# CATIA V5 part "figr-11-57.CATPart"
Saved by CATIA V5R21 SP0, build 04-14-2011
Part number: Part1
Bounding box of the stored display mesh (mm): x -55 to 55, y -105 to 155, z -20 to 14.953
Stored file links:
  D:\CATIA V5R21 E-RESOURCES\CATIA-V5R21\catia-v5r21-prt\c11-catia-v5r21-prt\c11-catia-v5r21-figr-11-57.CATPart
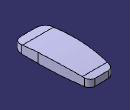
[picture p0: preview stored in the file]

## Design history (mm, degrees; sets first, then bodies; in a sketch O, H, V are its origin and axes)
Set1
  Extrude1: Element1 Sketch2, Lim1 50, Lim2 50, Direction yz-plane
  Sketch1 on xy-plane, origin (0, 0, 0), H (1, 0, 0), V (0, 1, 0)
    arc A1 centre (25, -75) radius 25 from (25, -100) to (50, -75) ccw
    line L1 (50, -75) -> (50, -15)
    point P4 (50, -15)
    arc A2 centre (-950, -15) radius 1000 from (50, -15) to (38.3367, 137.2843) ccw
    line L2 (23.5117, 150) -> (-23.5117, 150)
    line L3 (25, -100) -> (-25, -100)
    arc A3 centre (-25, -75) radius 25 from (-25, -100) to (-50, -75) cw
    line L4 (-50, -75) -> (-50, -15)
    point P9 (-50, -15)
    arc A4 centre (950, -15) radius 1000 from (-50, -15) to (-38.3367, 137.2843) cw
    reference projected line E1 (-50, -100) -> (50, -100) from edge of Extrude1
    axis line L5 (0, 170.4214) -> (0, -120.6595)
    point P11 (0, 170.4214)
    reference projected line E2 (50, -70) -> (50, 129.9971) from edge of Extrude1
    reference projected line E3 (-50, 129.9971) -> (-50, -70) from edge of Extrude1
    reference projected line E4 (-50, -100) -> (50, -100) from edge of Extrude1
    reference projected line E5 (50, 150) -> (-50, 150) from edge of Extrude1
    arc A5 centre (-23.5117, 135) radius 15 from (-38.3367, 137.2843) to (-23.5117, 150) cw
    arc A6 centre (23.5117, 135) radius 15 from (38.3367, 137.2843) to (23.5117, 150) ccw
    distance E4 P4 = 85
    radius A2 = 1000
    radius A5 = 15
    radius A6 = 15
    radius A1 = 25
    radius A3 = 25
    radius A4 = 1000
    tangency: L1 A1, A2 L1, L3 A1, A3 L3, A4 L4, L5 A3, A5 L2, A5 A4, A6 A2, A6 L2, A3 L4
    horizontal: L2 H
    coincidence: L3 E1, P11 V, L1 E2, L4 E3, L2 E5
    symmetry: P4 P9 L5
  Extrude2: Element1 Sketch1, Lim1 50, Lim2 20, Direction xy-plane
  Split1: ToCut Extrude2, Cutting Extrude1
  Split2: ToCut Extrude1, Cutting Split1
  Join1: Elements (Split2; Split1)
Body1 (main body)
  Sketch2 on yz-plane, origin (0, 0, 0), H (0, 1, 0), V (0, 0, 1)
    point P1 (-100, 0)
    line L1 (-100, 0) -> (-70, 3.8724)
    point P2 (-70, 3.8724)
    arc A1 centre (26.0141, -739.9564) radius 750 from (-70, 3.8724) to (129.9971, 2.8003) cw
    point P4 (129.9971, 2.8003)
    line L2 (129.9971, 2.8003) -> (150, 0)
    point P5 (150, 0)
    distance P1 P5 = 250
    distance P1 O = 100
    radius A1 = 750
    distance P2 P4 = 200
    distance P2 V = 70
    coincidence: P1 H, P5 H
    tangency: A1 L1, L2 A1
  ThickSurface1: BotOffset 0, Surface Join1, TopOffset 5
